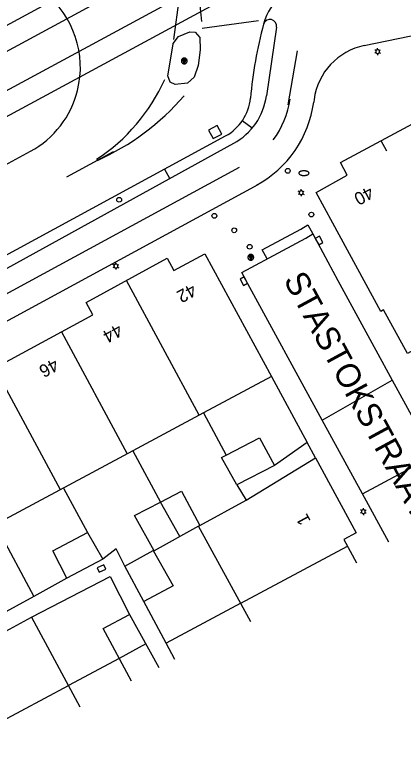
# Model space of a CAD drawing. Extents: x 81065 to 81486, y 452384 to 452681.
# Drawn here: x 81269.54 to 81293.93, y 452464.49 to 452511.24 of the extents above; entities that cross this region are included whole.
import ezdxf

# ---------------------------------------------------------------- set-up
doc = ezdxf.new("R2010")
doc.units = 0
for name, color, linetype in [('B-BH-AL-TOPOGRAFIE_HUISNUMMER-T25', 7, 'Continuous'), ('B-BH-AL-TOPOGRAFIE_STRAATNAAM-S', 7, 'Continuous'), ('B-BH-IE-MEUBILAIR-WEGMEUBILAIR-VERKEERSBORD-S', 7, 'Continuous'), ('B-BH-IE-MEUBILAIR_WEGMEUBILAIR_LICHTMAST-S', 7, 'Continuous'), ('B-BH-IE-MEUBILAIR_WEGMEUBILAIR_PAAL-S', 7, 'Continuous'), ('B-BH-KL-WATER_BRANDLEIDING_PUT-S', 7, 'Continuous'), ('B-BH-OG-TERREIN_ERF-GV', 7, 'Continuous'), ('B-BH-OG-TOPOGRAFIE_BEBOUWING-GV', 7, 'Continuous'), ('B-BH-OG-TOPOGRAFIE_BEBOUWING_PANDSCHEIDING-GV', 7, 'Continuous'), ('B-BH-RI-GWA_RIOOLPUT-S', 7, 'Continuous'), ('B-BH-VH-KANTOPSLUITING-GV', 7, 'Continuous'), ('B-SB-OG-WEG_SPOOR_TRAM-G', 7, 'Continuous'), ('B-SRI-KOLK_COMBINATIE-S', 7, 'Continuous'), ('B-WE-VW-MARKERING_DWARS_DRIEHOEK_5050-G', 7, 'Continuous'), ('B-WE-VW-MARKERING_LANGS_STREEP_11_010-G', 7, 'Continuous'), ('B-WE-VW-MARKERING_LANGS_STREEP_13_010-G', 7, 'Continuous'), ('B-WE-VW-MARKERING_LANGS_STREEP_30270_010-G', 7, 'Continuous'), ('B-WE-VW-MARKERING_LANGS_STREEP_DOORGETROKKEN_010-G', 7, 'Continuous')]:
    doc.layers.add(name, color=color, linetype=linetype)

msp = doc.modelspace()

# ---------------------------------------------------------------- linework, layer by layer
at = {"layer": 'B-BH-IE-MEUBILAIR-WEGMEUBILAIR-VERKEERSBORD-S'}
for p, q in [((81280.043, 452508.472), (81280.308, 452508.472)), ((81280.176, 452508.163), (81280.065, 452508.454)), ((81280.065, 452508.454), (81280.281, 452508.454)), ((81280.092, 452508.436), (81280.253, 452508.436)), ((81280.177, 452508.212), (81280.092, 452508.436)), ((81280.178, 452508.261), (81280.118, 452508.417)), ((81280.118, 452508.417), (81280.225, 452508.417)), ((81280.179, 452508.31), (81280.145, 452508.399)), ((81280.145, 452508.399), (81280.197, 452508.399)), ((81280.18, 452508.358), (81280.171, 452508.381)), ((81280.308, 452508.472), (81280.176, 452508.163)), ((81280.281, 452508.454), (81280.177, 452508.212)), ((81280.253, 452508.436), (81280.178, 452508.261)), ((81280.225, 452508.417), (81280.179, 452508.31)), ((81280.197, 452508.399), (81280.18, 452508.358)), ((81284.223, 452496.138), (81284.488, 452496.138)), ((81284.488, 452496.138), (81284.356, 452495.829)), ((81284.356, 452495.829), (81284.245, 452496.12)), ((81284.245, 452496.12), (81284.461, 452496.12)), ((81284.272, 452496.102), (81284.433, 452496.102)), ((81284.357, 452495.878), (81284.272, 452496.102)), ((81284.358, 452495.927), (81284.298, 452496.083)), ((81284.298, 452496.083), (81284.405, 452496.083)), ((81284.359, 452495.976), (81284.325, 452496.065)), ((81284.325, 452496.065), (81284.377, 452496.065)), ((81284.36, 452496.024), (81284.351, 452496.047)), ((81284.461, 452496.12), (81284.357, 452495.878)), ((81284.433, 452496.102), (81284.358, 452495.927)), ((81284.405, 452496.083), (81284.359, 452495.976)), ((81284.377, 452496.065), (81284.36, 452496.024))]:
    msp.add_line(p, q, dxfattribs=at)
for points in [[(81279.993, 452508.346), (81279.994, 452508.327), (81279.997, 452508.308), (81280.002, 452508.289), (81280.009, 452508.271), (81280.017, 452508.254), (81280.028, 452508.238), (81280.04, 452508.223), (81280.053, 452508.21), (81280.068, 452508.198), (81280.084, 452508.187), (81280.101, 452508.179), (81280.119, 452508.172), (81280.138, 452508.167), (81280.157, 452508.164), (81280.176, 452508.163), (81280.195, 452508.164), (81280.214, 452508.167), (81280.233, 452508.172), (81280.25, 452508.179), (81280.267, 452508.187), (81280.284, 452508.198), (81280.298, 452508.21), (81280.312, 452508.223), (81280.324, 452508.238), (81280.334, 452508.254), (81280.343, 452508.271), (81280.35, 452508.289), (81280.355, 452508.308), (81280.358, 452508.327), (81280.359, 452508.346), (81280.358, 452508.365), (81280.355, 452508.384), (81280.35, 452508.403), (81280.343, 452508.42), (81280.334, 452508.437), (81280.324, 452508.454), (81280.312, 452508.468), (81280.298, 452508.482), (81280.284, 452508.494), (81280.267, 452508.504), (81280.25, 452508.513), (81280.233, 452508.52), (81280.214, 452508.525), (81280.195, 452508.528), (81280.176, 452508.529), (81280.157, 452508.528), (81280.138, 452508.525), (81280.119, 452508.52), (81280.101, 452508.513), (81280.084, 452508.504), (81280.068, 452508.494), (81280.053, 452508.482), (81280.04, 452508.468), (81280.028, 452508.454), (81280.017, 452508.437), (81280.009, 452508.42), (81280.002, 452508.403), (81279.997, 452508.384), (81279.994, 452508.365), (81279.993, 452508.346)], [(81284.173, 452496.012), (81284.174, 452495.993), (81284.177, 452495.974), (81284.182, 452495.955), (81284.189, 452495.937), (81284.197, 452495.92), (81284.208, 452495.904), (81284.22, 452495.889), (81284.233, 452495.876), (81284.248, 452495.864), (81284.264, 452495.853), (81284.281, 452495.845), (81284.299, 452495.838), (81284.318, 452495.833), (81284.337, 452495.83), (81284.356, 452495.829), (81284.375, 452495.83), (81284.394, 452495.833), (81284.413, 452495.838), (81284.43, 452495.845), (81284.447, 452495.853), (81284.464, 452495.864), (81284.478, 452495.876), (81284.492, 452495.889), (81284.504, 452495.904), (81284.514, 452495.92), (81284.523, 452495.937), (81284.53, 452495.955), (81284.535, 452495.974), (81284.538, 452495.993), (81284.539, 452496.012), (81284.538, 452496.031), (81284.535, 452496.05), (81284.53, 452496.069), (81284.523, 452496.086), (81284.514, 452496.103), (81284.504, 452496.12), (81284.492, 452496.134), (81284.478, 452496.148), (81284.464, 452496.16), (81284.447, 452496.17), (81284.43, 452496.179), (81284.413, 452496.186), (81284.394, 452496.191), (81284.375, 452496.194), (81284.356, 452496.195), (81284.337, 452496.194), (81284.318, 452496.191), (81284.299, 452496.186), (81284.281, 452496.179), (81284.264, 452496.17), (81284.248, 452496.16), (81284.233, 452496.148), (81284.22, 452496.134), (81284.208, 452496.12), (81284.197, 452496.103), (81284.189, 452496.086), (81284.182, 452496.069), (81284.177, 452496.05), (81284.174, 452496.031), (81284.173, 452496.012)]]:
    msp.add_lwpolyline(points, dxfattribs=at)
at = {"layer": 'B-BH-IE-MEUBILAIR_WEGMEUBILAIR_LICHTMAST-S'}
for p, q in [((81292.22, 452508.993), (81292.14, 452509.039)), ((81292.22, 452508.871), (81292.14, 452508.825)), ((81292.325, 452509.054), (81292.325, 452509.146)), ((81292.325, 452508.81), (81292.325, 452508.718)), ((81292.431, 452508.993), (81292.51, 452509.039)), ((81292.431, 452508.871), (81292.51, 452508.825)), ((81287.417, 452500.129), (81287.338, 452500.175)), ((81287.417, 452500.007), (81287.338, 452499.961)), ((81287.523, 452500.19), (81287.523, 452500.282)), ((81287.523, 452499.946), (81287.523, 452499.854)), ((81287.628, 452500.129), (81287.708, 452500.175)), ((81287.628, 452500.007), (81287.708, 452499.961)), ((81275.881, 452495.584), (81275.881, 452495.675)), ((81275.776, 452495.523), (81275.696, 452495.569)), ((81275.776, 452495.401), (81275.696, 452495.355)), ((81275.881, 452495.34), (81275.881, 452495.248)), ((81275.987, 452495.523), (81276.066, 452495.569)), ((81275.987, 452495.401), (81276.066, 452495.355)), ((81291.427, 452480.159), (81291.427, 452480.251)), ((81291.321, 452480.098), (81291.242, 452480.144)), ((81291.321, 452479.976), (81291.242, 452479.93)), ((81291.427, 452479.915), (81291.427, 452479.823)), ((81291.532, 452480.098), (81291.612, 452480.144)), ((81291.532, 452479.976), (81291.612, 452479.93))]:
    msp.add_line(p, q, dxfattribs=at)
for points in [[(81292.203, 452508.932), (81292.204, 452508.919), (81292.206, 452508.907), (81292.209, 452508.894), (81292.214, 452508.882), (81292.22, 452508.871), (81292.226, 452508.86), (81292.235, 452508.85), (81292.244, 452508.841), (81292.254, 452508.833), (81292.264, 452508.826), (81292.276, 452508.821), (81292.287, 452508.816), (81292.3, 452508.813), (81292.313, 452508.811), (81292.325, 452508.81), (81292.338, 452508.811), (81292.351, 452508.813), (81292.363, 452508.816), (81292.375, 452508.821), (81292.386, 452508.826), (81292.397, 452508.833), (81292.407, 452508.841), (81292.416, 452508.85), (81292.424, 452508.86), (81292.431, 452508.871), (81292.437, 452508.882), (81292.441, 452508.894), (81292.445, 452508.907), (81292.447, 452508.919), (81292.447, 452508.932), (81292.447, 452508.945), (81292.445, 452508.957), (81292.441, 452508.97), (81292.437, 452508.982), (81292.431, 452508.993), (81292.424, 452509.004), (81292.416, 452509.014), (81292.407, 452509.023), (81292.397, 452509.031), (81292.386, 452509.038), (81292.375, 452509.044), (81292.363, 452509.048), (81292.351, 452509.051), (81292.338, 452509.053), (81292.325, 452509.054), (81292.313, 452509.053), (81292.3, 452509.051), (81292.287, 452509.048), (81292.276, 452509.044), (81292.264, 452509.038), (81292.254, 452509.031), (81292.244, 452509.023), (81292.235, 452509.014), (81292.226, 452509.004), (81292.22, 452508.993), (81292.214, 452508.982), (81292.209, 452508.97), (81292.206, 452508.957), (81292.204, 452508.945), (81292.203, 452508.932)], [(81287.401, 452500.068), (81287.402, 452500.055), (81287.403, 452500.042), (81287.407, 452500.03), (81287.411, 452500.018), (81287.417, 452500.007), (81287.424, 452499.996), (81287.432, 452499.986), (81287.441, 452499.977), (81287.451, 452499.969), (81287.462, 452499.962), (81287.473, 452499.956), (81287.485, 452499.952), (81287.498, 452499.948), (81287.51, 452499.947), (81287.523, 452499.946), (81287.536, 452499.947), (81287.548, 452499.948), (81287.561, 452499.952), (81287.573, 452499.956), (81287.584, 452499.962), (81287.595, 452499.969), (81287.605, 452499.977), (81287.614, 452499.986), (81287.622, 452499.996), (81287.629, 452500.007), (81287.634, 452500.018), (81287.639, 452500.03), (81287.642, 452500.042), (81287.644, 452500.055), (81287.645, 452500.068), (81287.644, 452500.081), (81287.642, 452500.093), (81287.639, 452500.106), (81287.634, 452500.118), (81287.629, 452500.129), (81287.622, 452500.14), (81287.614, 452500.15), (81287.605, 452500.159), (81287.595, 452500.167), (81287.584, 452500.174), (81287.573, 452500.179), (81287.561, 452500.184), (81287.548, 452500.187), (81287.536, 452500.189), (81287.523, 452500.19), (81287.51, 452500.189), (81287.497, 452500.187), (81287.485, 452500.184), (81287.473, 452500.179), (81287.462, 452500.174), (81287.451, 452500.167), (81287.441, 452500.159), (81287.432, 452500.15), (81287.424, 452500.14), (81287.417, 452500.129), (81287.411, 452500.118), (81287.407, 452500.106), (81287.403, 452500.093), (81287.402, 452500.081), (81287.401, 452500.068)], [(81275.759, 452495.462), (81275.76, 452495.449), (81275.762, 452495.436), (81275.765, 452495.424), (81275.77, 452495.412), (81275.776, 452495.401), (81275.782, 452495.39), (81275.791, 452495.38), (81275.8, 452495.371), (81275.81, 452495.363), (81275.82, 452495.356), (81275.832, 452495.35), (81275.843, 452495.346), (81275.856, 452495.342), (81275.869, 452495.341), (81275.881, 452495.34), (81275.894, 452495.341), (81275.907, 452495.342), (81275.919, 452495.346), (81275.931, 452495.35), (81275.942, 452495.356), (81275.953, 452495.363), (81275.963, 452495.371), (81275.972, 452495.38), (81275.98, 452495.39), (81275.987, 452495.401), (81275.993, 452495.412), (81275.997, 452495.424), (81276.001, 452495.436), (81276.003, 452495.449), (81276.003, 452495.462), (81276.003, 452495.475), (81276.001, 452495.487), (81275.997, 452495.5), (81275.993, 452495.512), (81275.987, 452495.523), (81275.98, 452495.534), (81275.972, 452495.544), (81275.963, 452495.553), (81275.953, 452495.561), (81275.942, 452495.568), (81275.931, 452495.573), (81275.919, 452495.578), (81275.907, 452495.581), (81275.894, 452495.583), (81275.881, 452495.584), (81275.869, 452495.583), (81275.856, 452495.581), (81275.843, 452495.578), (81275.832, 452495.573), (81275.82, 452495.568), (81275.81, 452495.561), (81275.8, 452495.553), (81275.791, 452495.544), (81275.782, 452495.534), (81275.776, 452495.523), (81275.77, 452495.512), (81275.765, 452495.5), (81275.762, 452495.487), (81275.76, 452495.475), (81275.759, 452495.462)], [(81291.305, 452480.037), (81291.306, 452480.024), (81291.307, 452480.011), (81291.311, 452479.999), (81291.315, 452479.987), (81291.321, 452479.976), (81291.328, 452479.965), (81291.336, 452479.955), (81291.345, 452479.946), (81291.355, 452479.938), (81291.366, 452479.931), (81291.377, 452479.925), (81291.389, 452479.921), (81291.402, 452479.917), (81291.414, 452479.916), (81291.427, 452479.915), (81291.44, 452479.916), (81291.452, 452479.917), (81291.465, 452479.921), (81291.477, 452479.925), (81291.488, 452479.931), (81291.499, 452479.938), (81291.509, 452479.946), (81291.518, 452479.955), (81291.526, 452479.965), (81291.533, 452479.976), (81291.538, 452479.987), (81291.543, 452479.999), (81291.546, 452480.011), (81291.548, 452480.024), (81291.549, 452480.037), (81291.548, 452480.05), (81291.546, 452480.062), (81291.543, 452480.075), (81291.538, 452480.087), (81291.533, 452480.098), (81291.526, 452480.109), (81291.518, 452480.119), (81291.509, 452480.128), (81291.499, 452480.136), (81291.488, 452480.143), (81291.477, 452480.148), (81291.465, 452480.153), (81291.452, 452480.156), (81291.44, 452480.158), (81291.427, 452480.159), (81291.414, 452480.158), (81291.401, 452480.156), (81291.389, 452480.153), (81291.377, 452480.148), (81291.366, 452480.143), (81291.355, 452480.136), (81291.345, 452480.128), (81291.336, 452480.119), (81291.328, 452480.109), (81291.321, 452480.098), (81291.315, 452480.087), (81291.311, 452480.075), (81291.307, 452480.062), (81291.306, 452480.05), (81291.305, 452480.037)]]:
    msp.add_lwpolyline(points, dxfattribs=at)
at = {"layer": 'B-BH-IE-MEUBILAIR_WEGMEUBILAIR_PAAL-S'}
for centre in [(81286.68, 452501.443), (81276.087, 452499.627), (81282.069, 452498.617), (81288.161, 452498.697), (81283.316, 452497.709), (81284.284, 452496.672)]:
    msp.add_circle(centre, 0.15, dxfattribs=at)
at = {"layer": 'B-BH-KL-WATER_BRANDLEIDING_PUT-S'}
msp.add_lwpolyline([(81287.693, 452501.444), (81287.659, 452501.443), (81287.626, 452501.441), (81287.594, 452501.437), (81287.562, 452501.432), (81287.532, 452501.425), (81287.504, 452501.417), (81287.478, 452501.408), (81287.454, 452501.397), (81287.433, 452501.385), (81287.414, 452501.373), (81287.399, 452501.359), (81287.387, 452501.345), (81287.378, 452501.331), (81287.373, 452501.316), (81287.371, 452501.3), (81287.373, 452501.285), (81287.378, 452501.27), (81287.386, 452501.255), (81287.398, 452501.241), (81287.413, 452501.227), (81287.432, 452501.214), (81287.453, 452501.202), (81287.476, 452501.191), (81287.502, 452501.182), (81287.531, 452501.173), (81287.56, 452501.166), (81287.592, 452501.16), (81287.624, 452501.156), (81287.657, 452501.153), (81287.691, 452501.152), (81287.724, 452501.153), (81287.758, 452501.155), (81287.79, 452501.159), (81287.822, 452501.164), (81287.852, 452501.171), (81287.88, 452501.179), (81287.906, 452501.188), (81287.93, 452501.199), (81287.951, 452501.21), (81287.969, 452501.223), (81287.985, 452501.236), (81287.997, 452501.251), (81288.006, 452501.265), (81288.011, 452501.28), (81288.013, 452501.295), (81288.011, 452501.311), (81288.006, 452501.326), (81287.998, 452501.341), (81287.986, 452501.355), (81287.971, 452501.369), (81287.952, 452501.381), (81287.931, 452501.394), (81287.908, 452501.405), (81287.882, 452501.414), (81287.853, 452501.423), (81287.823, 452501.43), (81287.792, 452501.436), (81287.76, 452501.44), (81287.727, 452501.443), (81287.693, 452501.444)], dxfattribs=at)
at = {"layer": 'B-BH-OG-TERREIN_ERF-GV'}
for p, q in [((81281.39, 452486.233), (81282.813, 452483.591)), ((81276.953, 452483.856), (81278.686, 452480.636)), ((81272.59, 452481.52), (81274.102, 452478.718)), ((81268.304, 452479.225), (81270.728, 452474.716)), ((81278.282, 452477.58), (81278.214, 452477.589)), ((81283.723, 452474.285), (81279.032, 452471.783)), ((81276.091, 452470.817), (81272.898, 452469.114))]:
    msp.add_line(p, q, dxfattribs=at)
at = {"layer": 'B-BH-OG-TOPOGRAFIE_BEBOUWING-GV'}
for p, q in [((81285.665, 452488.523), (81281.39, 452486.233)), ((81285.846, 452482.933), (81283.487, 452481.71)), ((81281.145, 452479.17), (81284.067, 452480.754)), ((81281.076, 452479.132), (81281.145, 452479.17)), ((81274.102, 452478.718), (81275.065, 452477.043)), ((81276.449, 452476.612), (81278.214, 452477.589)), ((81275.065, 452477.043), (81272.808, 452475.859)), ((81277.644, 452474.382), (81276.449, 452476.612)), ((81270.573, 452473.41), (81273.626, 452467.767)), ((81276.738, 452473.577), (81278.582, 452470.238))]:
    msp.add_line(p, q, dxfattribs=at)
for points in [[(81295.749, 452490.824), (81294.191, 452489.974), (81292.702, 452492.703), (81292.52, 452492.606), (81289.503, 452498.156), (81288.453, 452500.086), (81290.406, 452501.174), (81289.998, 452501.96), (81295.103, 452504.706), (81295.52, 452503.931), (81299.207, 452505.932)], [(81259.141, 452474.46), (81255.077, 452481.918), (81257.035, 452482.985), (81256.613, 452483.737), (81261.697, 452486.487), (81262.103, 452485.714), (81274.44, 452492.398), (81274.017, 452493.17), (81279.096, 452495.951), (81279.515, 452495.177), (81281.473, 452496.234), (81285.665, 452488.523)], [(81281.39, 452486.233), (81276.953, 452483.856), (81268.304, 452479.225), (81263.915, 452476.874), (81259.141, 452474.46)], [(81282.813, 452483.591), (81284.895, 452484.671), (81285.846, 452482.933)], [(81283.487, 452481.71), (81282.511, 452483.435), (81282.813, 452483.591)], [(81284.067, 452480.754), (81288.414, 452483.423), (81290.981, 452478.696), (81290.208, 452478.276), (81290.996, 452476.83)], [(81278.686, 452480.636), (81279.996, 452481.313), (81281.145, 452479.17)], [(81281.076, 452479.132), (81278.282, 452477.58), (81277.057, 452479.794), (81278.686, 452480.636)], [(81284.36, 452473.119), (81281.076, 452479.132)], [(81272.808, 452475.859), (81271.921, 452477.573), (81274.102, 452478.718)], [(81278.214, 452477.589), (81279.485, 452475.373), (81277.644, 452474.382)], [(81265.075, 452463.503), (81263.137, 452467.056), (81263.918, 452467.482), (81262.951, 452469.255), (81270.573, 452473.41)], [(81276.862, 452469.381), (81275.086, 452472.689), (81276.738, 452473.577)]]:
    msp.add_lwpolyline(points, dxfattribs=at)
at = {"layer": 'B-BH-OG-TOPOGRAFIE_BEBOUWING_PANDSCHEIDING-GV'}
for p, q in [((81292.897, 452502.689), (81292.551, 452503.333)), ((81281.122, 452486.089), (81276.555, 452494.563)), ((81272.466, 452491.33), (81276.591, 452483.661)), ((81272.396, 452481.415), (81268.271, 452489.056)), ((81279.888, 452478.472), (81278.686, 452480.636)), ((81283.723, 452474.285), (81290.433, 452477.864)), ((81277.755, 452471.736), (81276.091, 452470.817)), ((81264.468, 452464.617), (81272.898, 452469.114))]:
    msp.add_line(p, q, dxfattribs=at)
at = {"layer": 'B-BH-RI-GWA_RIOOLPUT-S'}
for p, q in [((81282.24, 452504.291), (81281.705, 452504.003)), ((81282.528, 452503.756), (81282.24, 452504.291)), ((81281.705, 452504.003), (81281.993, 452503.468)), ((81281.993, 452503.468), (81282.528, 452503.756))]:
    msp.add_line(p, q, dxfattribs=at)
at = {"layer": 'B-BH-VH-KANTOPSLUITING-GV'}
for p, q in [((81291.488, 452509.315), (81303.606, 452511.817)), ((81285.978, 452510.462), (81285.336, 452506.155)), ((81288.333, 452505.933), (81288.309, 452505.754)), ((81284.436, 452504.119), (81283.82, 452504.582)), ((81261.363, 452492.008), (81282.776, 452503.64)), ((81254.451, 452487.309), (81283.281, 452503.175)), ((81253.855, 452493.619), (81270.515, 452502.67)), ((81278.931, 452501.551), (81279.241, 452500.98)), ((81255.064, 452484.432), (81284.809, 452500.591)), ((81285.665, 452488.523), (81287.894, 452484.381)), ((81288.845, 452485.786), (81293.235, 452488.298)), ((81293.235, 452488.298), (81295.818, 452483.556)), ((81291.371, 452481.154), (81288.845, 452485.786)), ((81287.894, 452484.381), (81285.846, 452482.933)), ((81288.414, 452483.423), (81287.894, 452484.381)), ((81291.371, 452481.154), (81295.818, 452483.556)), ((81283.487, 452481.71), (81284.067, 452480.754)), ((81293.028, 452478.116), (81291.371, 452481.154)), ((81272.808, 452475.859), (81270.728, 452474.716)), ((81270.728, 452474.716), (81268.483, 452473.481)), ((81279.032, 452471.783), (81277.644, 452474.382)), ((81279.589, 452470.74), (81279.032, 452471.783))]:
    msp.add_line(p, q, dxfattribs=at)
for points in [[(81279.816, 452509.872), (81280.53, 452510.18), (81280.863, 452510.155), (81281.146, 452509.823), (81281.185, 452509.053), (81281.052, 452508.057), (81280.806, 452507.329), (81280.376, 452506.956), (81279.596, 452506.867), (81279.293, 452507.007), (81279.151, 452507.414), (81279.474, 452509.403), (81279.486, 452509.448), (81279.816, 452509.872)], [(81285.071, 452496.49), (81287.492, 452497.788), (81287.947, 452498.05)], [(81287.947, 452498.05), (81288.256, 452497.478)], [(81283.792, 452495.067), (81287.808, 452497.22), (81288.256, 452497.478)], [(81288.256, 452497.478), (81289.83, 452494.565), (81292.215, 452490.17), (81293.235, 452488.298)], [(81285.378, 452495.917), (81285.071, 452496.49)], [(81288.845, 452485.786), (81284.052, 452494.582), (81283.792, 452495.067)], [(81276.449, 452476.612), (81275.896, 452477.696), (81275.065, 452477.043)], [(81270.573, 452473.41), (81275.517, 452475.971), (81276.738, 452473.577)]]:
    msp.add_lwpolyline(points, dxfattribs=at)
for centre, radius, start, end in [((81267.651, 452507.942), 6, 346.0023, 51.5109), ((81288.701, 452509.696), 3.67, 129.4501, 164.6954), ((81311.749, 452503.528), 27.529, 164.9757, 174.8353), ((81285.562, 452510.533), 0.422, 350.276, 161.8682), ((81292.297, 452505.398), 4, 101.6661, 172.3174), ((81267.651, 452507.942), 6, 298.5132, 346.0023), ((81281.344, 452506.277), 3, 298.5132, 354.8353), ((81281.371, 452506.69), 4, 298.5132, 352.3174), ((81281.371, 452506.69), 7, 298.5132, 352.3174)]:
    msp.add_arc(centre, radius, start, end, dxfattribs=at)
at = {"layer": 'B-SB-OG-WEG_SPOOR_TRAM-G'}
for p, q in [((81288.285, 452521.011), (81250, 452500.286)), ((81288.969, 452519.749), (81250, 452498.654)), ((81250, 452496.192), (81288.558, 452517.065)), ((81250, 452494.56), (81289.242, 452515.803))]:
    msp.add_line(p, q, dxfattribs=at)
at = {"layer": 'B-SRI-KOLK_COMBINATIE-S'}
for p, q in [((81288.668, 452497.338), (81288.409, 452497.196)), ((81288.409, 452497.196), (81288.623, 452496.803)), ((81288.882, 452496.944), (81288.668, 452497.338)), ((81288.623, 452496.803), (81288.882, 452496.944)), ((81283.947, 452494.779), (81283.687, 452494.64)), ((81284.158, 452494.384), (81283.947, 452494.779)), ((81283.687, 452494.64), (81283.898, 452494.245)), ((81283.898, 452494.245), (81284.158, 452494.384)), ((81275.125, 452476.691), (81274.715, 452476.512)), ((81274.715, 452476.512), (81274.833, 452476.242)), ((81275.243, 452476.42), (81275.125, 452476.691)), ((81274.833, 452476.242), (81275.243, 452476.42))]:
    msp.add_line(p, q, dxfattribs=at)
at = {"layer": 'B-WE-VW-MARKERING_DWARS_DRIEHOEK_5050-G'}
msp.add_lwpolyline([(81281.3, 452510.403), (81284.84, 452510.892)], dxfattribs=at)
at = {"layer": 'B-WE-VW-MARKERING_LANGS_STREEP_11_010-G'}
for centre, radius, start, end in [((81268.218, 452511.994), 11.758, 303.299, 335.844), ((81268.33, 452516.331), 15.601, 294.1614, 319.3243)]:
    msp.add_arc(centre, radius, start, end, dxfattribs=at)
at = {"layer": 'B-WE-VW-MARKERING_LANGS_STREEP_13_010-G'}
msp.add_line((81272.807, 452501.07), (81275.741, 452502.664), dxfattribs=at)
at = {"layer": 'B-WE-VW-MARKERING_LANGS_STREEP_30270_010-G'}
for p, q in [((81286.705, 452505.585), (81287.281, 452508.973)), ((81283.619, 452501.652), (81255.207, 452486.216))]:
    msp.add_line(p, q, dxfattribs=at)
msp.add_arc((81281.371, 452506.69), 5.5, 323.0398, 352.3174, dxfattribs=at)
at = {"layer": 'B-WE-VW-MARKERING_LANGS_STREEP_DOORGETROKKEN_010-G'}
msp.add_line((81280.086, 452513.991), (81279.507, 452509.697), dxfattribs=at)
msp.add_arc((81257.338, 452508.824), 24.031, 4.7533, 12.7482, dxfattribs=at)

# ---------------------------------------------------------------- texts
at = {"layer": 'B-BH-AL-TOPOGRAFIE_HUISNUMMER-T25'}
for s, rotation, p in [('40', 208.4161, (81291.804, 452500.51)), ('42', 208.4731, (81280.67, 452494.381)), ('44', 208.4731, (81276.024, 452491.862)), ('46', 208.4731, (81272.016, 452489.688)), ('1', 118.5961, (81288.143, 452479.455))]:
    msp.add_text(s, height=0.8, rotation=rotation, dxfattribs=at).set_placement(p)
at = {"layer": 'B-BH-AL-TOPOGRAFIE_STRAATNAAM-S'}
msp.add_text('STASTOKSTRAAT', height=1.5, rotation=298.4741, dxfattribs=at).set_placement((81286.385, 452494.592))

doc.saveas('drawing.dxf')
